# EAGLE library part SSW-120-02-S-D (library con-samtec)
THROUGH-HOLE .025" SQ POST SOCKET Source: Samtec SSW.pdf
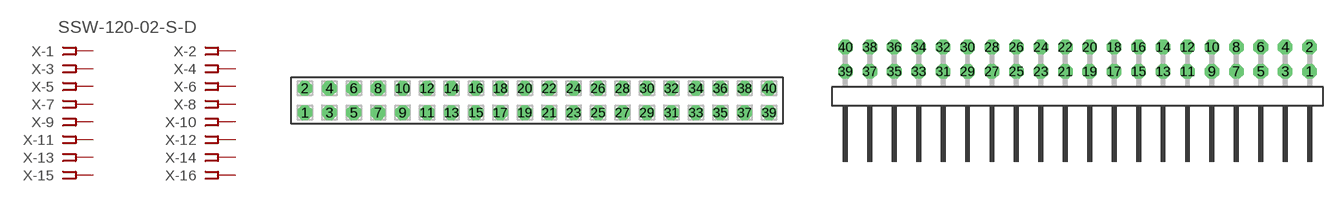
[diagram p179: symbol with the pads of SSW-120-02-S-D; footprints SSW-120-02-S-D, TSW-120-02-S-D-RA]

Designator prefix X; gates -1=FPINV -2=FPIN -3=FPIN -4=FPIN -5=FPIN -6=FPIN -7=FPIN -8=FPIN -9=FPIN -10=FPIN -11=FPIN -12=FPIN -13=FPIN -14=FPIN -15=FPIN -16=FPIN -17=FPIN -18=FPIN -19=FPIN -20=FPIN -21=FPIN -22=FPIN -23=FPIN -24=FPIN -25=FPIN -26=FPIN -27=FPIN -28=FPIN -29=FPIN -30=FPIN -31=FPIN -32=FPIN -33=FPIN -34=FPIN -35=FPIN -36=FPIN -37=FPIN -38=FPIN -39=FPIN -40=FPIN

## SSW-120-02-S-D (MPN: SSW-120-02-S-D; OC_FARNELL: unknown; OC_NEWARK: 11P9639)  [SSW-120-02-S-D]
1  -1:1  pas
2  -2:1  pas
3  -3:1  pas
4  -4:1  pas
5  -5:1  pas
6  -6:1  pas
7  -7:1  pas
8  -8:1  pas
9  -9:1  pas
10  -10:1  pas
11  -11:1  pas
12  -12:1  pas
13  -13:1  pas
14  -14:1  pas
15  -15:1  pas
16  -16:1  pas
17  -17:1  pas
18  -18:1  pas
19  -19:1  pas
20  -20:1  pas
21  -21:1  pas
22  -22:1  pas
23  -23:1  pas
24  -24:1  pas
25  -25:1  pas
26  -26:1  pas
27  -27:1  pas
28  -28:1  pas
29  -29:1  pas
30  -30:1  pas
31  -31:1  pas
32  -32:1  pas
33  -33:1  pas
34  -34:1  pas
35  -35:1  pas
36  -36:1  pas
37  -37:1  pas
38  -38:1  pas
39  -39:1  pas
40  -40:1  pas

## SSW-120-02-S-D-RA (MPN: SSW-120-02-S-D-RA; OC_FARNELL: unknown; OC_NEWARK: 11P9640)  [TSW-120-02-S-D-RA]
Pads as for SSW-120-02-S-D

## Footprint SSW-120-02-S-D (pad centres in mm)
THROUGH-HOLE .025" SQ POST SOCKET Source: Samtec SSW.pdf
drill 1 pad 1.5 octagon: 1 -24.13,-1.27; 2 -24.13,1.27; 3 -21.59,-1.27; 4 -21.59,1.27; 5 -19.05,-1.27; 6 -19.05,1.27; 7 -16.51,-1.27; 8 -16.51,1.27; 9 -13.97,-1.27; 10 -13.97,1.27; 11 -11.43,-1.27; 12 -11.43,1.27; 13 -8.89,-1.27; 14 -8.89,1.27; 15 -6.35,-1.27; 16 -6.35,1.27; 17 -3.81,-1.27; 18 -3.81,1.27; 19 -1.27,-1.27; 20 -1.27,1.27; 21 1.27,-1.27; 22 1.27,1.27; 23 3.81,-1.27; 24 3.81,1.27; 25 6.35,-1.27; 26 6.35,1.27; 27 8.89,-1.27; 28 8.89,1.27; 29 11.43,-1.27; 30 11.43,1.27; 31 13.97,-1.27; 32 13.97,1.27; 33 16.51,-1.27; 34 16.51,1.27; 35 19.05,-1.27; 36 19.05,1.27; 37 21.59,-1.27; 38 21.59,1.27; 39 24.13,-1.27; 40 24.13,1.27

## Footprint TSW-120-02-S-D-RA (pad centres in mm)
THROUGH-HOLE .025" SQ POST HEADER Source: Samtec TSW.pdf
drill 1 pad 1.5 octagon: 1 24.13,1.524; 2 24.13,4.064; 3 21.59,1.524; 4 21.59,4.064; 5 19.05,1.524; 6 19.05,4.064; 7 16.51,1.524; 8 16.51,4.064; 9 13.97,1.524; 10 13.97,4.064; 11 11.43,1.524; 12 11.43,4.064; 13 8.89,1.524; 14 8.89,4.064; 15 6.35,1.524; 16 6.35,4.064; 17 3.81,1.524; 18 3.81,4.064; 19 1.27,1.524; 20 1.27,4.064; 21 -1.27,1.524; 22 -1.27,4.064; 23 -3.81,1.524; 24 -3.81,4.064; 25 -6.35,1.524; 26 -6.35,4.064; 27 -8.89,1.524; 28 -8.89,4.064; 29 -11.43,1.524; 30 -11.43,4.064; 31 -13.97,1.524; 32 -13.97,4.064; 33 -16.51,1.524; 34 -16.51,4.064; 35 -19.05,1.524; 36 -19.05,4.064; 37 -21.59,1.524; 38 -21.59,4.064; 39 -24.13,1.524; 40 -24.13,4.064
